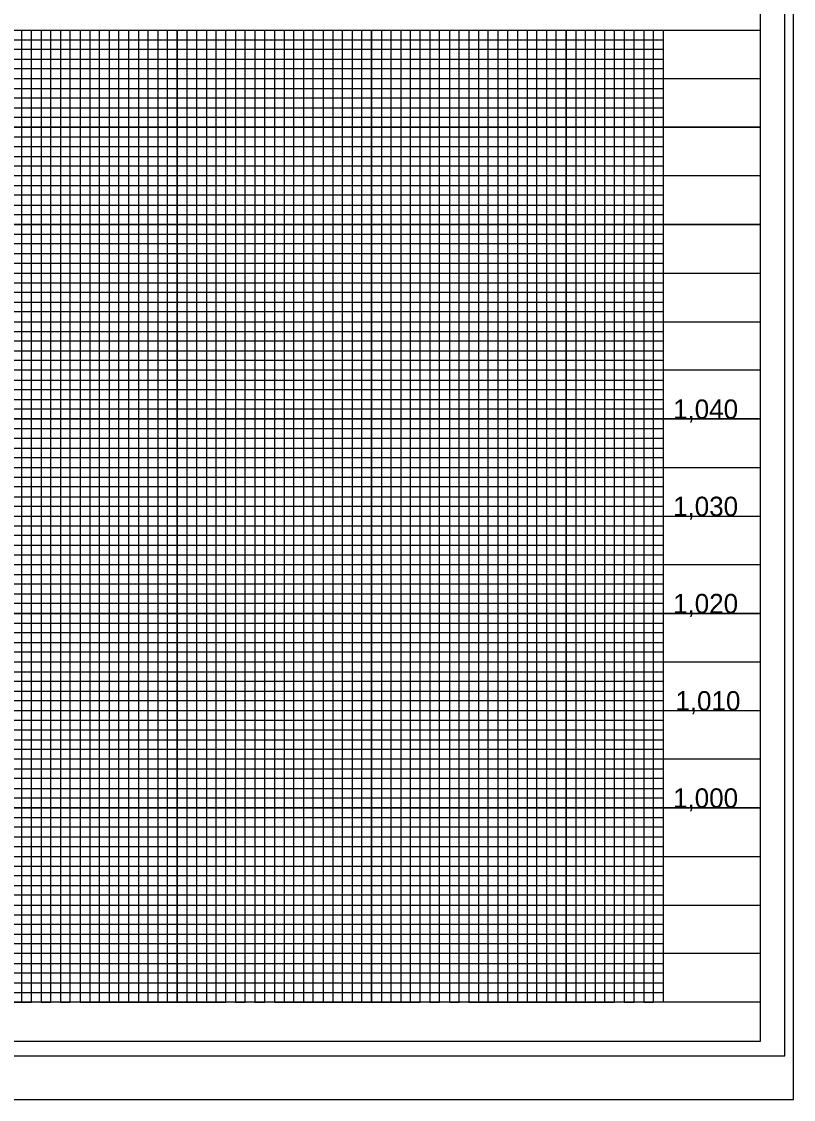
# Model space of a CAD drawing. Extents: x 1427348 to 1429459, y 856278 to 857378.
# Drawn here: x 1428884 to 1429281, y 856278 to 856832 of the extents above; entities that cross this region are included whole.
import ezdxf

# ---------------------------------------------------------------- set-up
doc = ezdxf.new("R2010")
doc.units = 0
for name, color, linetype in [('Exist Vertical Profile Vertical Axis Label', 7, 'Continuous'), ('Sheet Cutting Line CELL', 7, 'Continuous'), ('Sheet DOT Grid CELL', 7, 'Continuous'), ('Sheet Layout Profile Border Port 2', 7, 'Continuous'), ('Sheet Plot Border Inside CELL', 7, 'Continuous'), ('Sheet Plot Border Outside CELL', 7, 'Continuous'), ('Sheet Profile CELL', 7, 'Continuous'), ('Sheet Profile Grid Major CELL', 7, 'Continuous'), ('Sheet Profile Grid Middle CELL', 7, 'Continuous'), ('Sheet Profile Grid Minor CELL', 7, 'Continuous')]:
    doc.layers.add(name, color=color, linetype=linetype)

msp = doc.modelspace()

# ---------------------------------------------------------------- linework, layer by layer
at = {"layer": 'Sheet Cutting Line CELL'}
msp.add_line((1427596.99, 856277.58), (1429280.99, 856277.58), dxfattribs=at)
at = {"layer": 'Sheet DOT Grid CELL'}
for p, q in [((1427763.99, 856827.58), (1429263.88, 856827.58)), ((1428913.99, 856827.58), (1428913.99, 856327.58)), ((1428963.99, 856827.58), (1428963.99, 856327.58)), ((1429013.99, 856827.58), (1429013.99, 856327.58)), ((1429063.99, 856827.58), (1429063.99, 856327.58)), ((1429113.99, 856827.58), (1429113.99, 856327.58)), ((1429163.99, 856827.58), (1429163.99, 856327.58)), ((1429213.99, 856827.58), (1429213.99, 856327.58)), ((1427763.99, 856777.58), (1429263.88, 856777.58)), ((1428458.77, 856727.58), (1429263.88, 856727.58)), ((1428023.59, 856677.58), (1429263.88, 856677.58)), ((1428485.43, 856627.58), (1429263.88, 856627.58)), ((1428403.82, 856577.58), (1429263.88, 856577.58)), ((1427763.99, 856527.58), (1429263.88, 856527.58)), ((1427763.99, 856477.58), (1429263.88, 856477.58)), ((1427763.99, 856427.58), (1429263.88, 856427.58)), ((1427763.99, 856377.58), (1429263.88, 856377.58))]:
    msp.add_line(p, q, dxfattribs=at)
at = {"layer": 'Sheet Layout Profile Border Port 2'}
msp.add_lwpolyline([(1427813.99, 856827.58), (1429213.99, 856827.58), (1429213.99, 856327.58), (1427813.99, 856327.58)], close=True, dxfattribs=at)
at = {"layer": 'Sheet Plot Border Inside CELL'}
for p, q in [((1429276.49, 856300.03), (1429276.49, 857355.13)), ((1427609.99, 856300.03), (1429276.49, 856300.03))]:
    msp.add_line(p, q, dxfattribs=at)
at = {"layer": 'Sheet Plot Border Outside CELL'}
msp.add_lwpolyline([(1427596.99, 856277.58), (1429280.99, 856277.58), (1429280.99, 857377.58), (1427596.99, 857377.58)], close=True, dxfattribs=at)
at = {"layer": 'Sheet Profile CELL'}
for p, q in [((1427763.99, 856827.58), (1429263.99, 856827.58)), ((1429263.99, 856327.58), (1427763.99, 856327.58)), ((1427763.99, 856307.58), (1429263.99, 856307.58))]:
    msp.add_line(p, q, dxfattribs=at)
msp.add_lwpolyline([(1429263.99, 857347.58), (1427763.99, 857347.58), (1427763.99, 856307.58), (1429263.99, 856307.58)], close=True, dxfattribs=at)
at = {"layer": 'Sheet Profile Grid Major CELL'}
for p, q in [((1428863.99, 856827.58), (1428913.99, 856827.58)), ((1428963.99, 856827.58), (1429013.99, 856827.58)), ((1429063.99, 856827.58), (1429113.99, 856827.58)), ((1429163.99, 856827.58), (1429213.99, 856827.58)), ((1429163.99, 856327.58), (1429163.99, 856327.58))]:
    msp.add_line(p, q, dxfattribs=at)
for points in [[(1428863.99, 856827.58), (1428913.99, 856827.58), (1428913.99, 856327.58), (1428963.99, 856327.58), (1428963.99, 856827.58), (1429013.99, 856827.58), (1429013.99, 856327.58), (1429063.99, 856327.58), (1429063.99, 856827.58), (1429113.99, 856827.58), (1429113.99, 856327.58), (1429163.99, 856327.58), (1429163.99, 856327.58), (1429163.99, 856827.58), (1429213.99, 856827.58), (1429213.99, 856327.58)], [(1429263.99, 856777.58), (1427763.99, 856777.58)], [(1429263.99, 856727.58), (1428458.77, 856727.58)], [(1428023.59, 856677.58), (1429263.99, 856677.58)], [(1429263.99, 856627.58), (1428485.43, 856627.58)], [(1428403.82, 856577.58), (1429263.99, 856577.58)], [(1429263.99, 856527.58), (1427763.99, 856527.58), (1427763.99, 856477.58), (1429263.99, 856477.58)], [(1429263.99, 856427.58), (1427763.99, 856427.58), (1427763.99, 856427.58), (1427763.99, 856377.58), (1429263.99, 856377.58)], [(1429263.99, 856327.58), (1427763.99, 856327.58)]]:
    msp.add_lwpolyline(points, dxfattribs=at)
at = {"layer": 'Sheet Profile Grid Middle CELL'}
for points in [[(1428838.99, 856327.58), (1428888.99, 856327.58), (1428888.99, 856827.58), (1428938.99, 856827.58), (1428938.99, 856327.58), (1428988.99, 856327.58), (1428988.99, 856827.58), (1429038.99, 856827.58), (1429038.99, 856327.58), (1429088.99, 856327.58), (1429088.99, 856827.58), (1429138.99, 856827.58), (1429138.99, 856327.58), (1429188.99, 856327.58), (1429188.99, 856827.58)], [(1427763.99, 856802.58), (1429263.99, 856802.58)], [(1429263.99, 856752.58), (1428458.77, 856752.58)], [(1428023.59, 856702.58), (1429263.99, 856702.58)], [(1429263.99, 856652.58), (1428485.43, 856652.58)], [(1428403.82, 856602.58), (1429263.99, 856602.58)], [(1429263.99, 856552.58), (1427763.99, 856552.58), (1427763.99, 856502.58), (1429263.99, 856502.58)], [(1429263.99, 856452.58), (1427763.99, 856452.58), (1427763.99, 856402.58), (1429263.99, 856402.58)], [(1429263.99, 856352.58), (1427763.99, 856352.58)]]:
    msp.add_lwpolyline(points, dxfattribs=at)
at = {"layer": 'Sheet Profile Grid Minor CELL'}
for p, q in [((1427813.99, 856822.58), (1429213.99, 856822.58)), ((1429213.99, 856817.58), (1427813.99, 856817.58)), ((1427813.99, 856812.58), (1429213.99, 856812.58)), ((1429213.99, 856807.58), (1427813.99, 856807.58)), ((1427813.99, 856797.58), (1429213.99, 856797.58)), ((1429213.99, 856792.58), (1427813.99, 856792.58)), ((1427813.99, 856787.58), (1429213.99, 856787.58)), ((1429213.99, 856782.58), (1427813.99, 856782.58)), ((1427813.99, 856772.58), (1429213.99, 856772.58)), ((1429213.99, 856767.58), (1427813.99, 856767.58)), ((1427813.99, 856762.58), (1429213.99, 856762.58)), ((1429213.99, 856757.58), (1428458.77, 856757.58)), ((1428458.77, 856747.58), (1429213.99, 856747.58)), ((1429213.99, 856742.58), (1428458.77, 856742.58)), ((1428458.77, 856737.58), (1429213.99, 856737.58)), ((1429213.99, 856732.58), (1428458.77, 856732.58)), ((1428458.77, 856722.58), (1429213.99, 856722.58)), ((1429213.99, 856717.58), (1428009.5, 856717.58)), ((1427813.99, 856712.58), (1429213.99, 856712.58)), ((1429213.99, 856707.58), (1428023.59, 856707.58)), ((1428023.59, 856697.58), (1429213.99, 856697.58)), ((1429213.99, 856692.58), (1428023.59, 856692.58)), ((1428023.59, 856687.58), (1429213.99, 856687.58)), ((1429213.99, 856682.58), (1428023.59, 856682.58)), ((1428362.68, 856672.58), (1429213.99, 856672.58)), ((1429213.99, 856667.58), (1428485.43, 856667.58)), ((1428485.43, 856662.58), (1429213.99, 856662.58)), ((1429213.99, 856657.58), (1428485.43, 856657.58)), ((1428485.43, 856647.58), (1429213.99, 856647.58)), ((1429213.99, 856642.58), (1428485.43, 856642.58)), ((1428485.43, 856637.58), (1429213.99, 856637.58)), ((1429213.99, 856632.58), (1428485.43, 856632.66)), ((1427813.99, 856622.58), (1429213.99, 856622.58)), ((1429213.99, 856617.58), (1427813.99, 856617.58)), ((1427813.99, 856612.58), (1429213.99, 856612.58)), ((1429213.99, 856607.58), (1428403.82, 856607.58)), ((1428403.82, 856597.58), (1429213.99, 856597.58)), ((1429213.99, 856592.58), (1428403.82, 856592.58)), ((1428403.82, 856587.58), (1429213.99, 856587.58)), ((1429213.99, 856582.58), (1428403.82, 856582.58)), ((1428403.82, 856572.58), (1429213.99, 856572.58)), ((1429213.99, 856567.58), (1428403.82, 856567.58)), ((1427813.99, 856562.58), (1429213.99, 856562.58)), ((1429213.99, 856557.58), (1427813.99, 856557.58)), ((1427813.99, 856547.58), (1429213.99, 856547.58)), ((1429213.99, 856542.58), (1427813.99, 856542.58)), ((1427813.99, 856537.58), (1429213.99, 856537.58)), ((1429213.99, 856532.58), (1427813.99, 856532.58)), ((1427813.99, 856522.58), (1429213.99, 856522.58)), ((1429213.99, 856517.58), (1427813.99, 856517.58)), ((1427813.99, 856512.58), (1429213.99, 856512.58)), ((1429213.99, 856507.58), (1427813.99, 856507.58)), ((1427813.99, 856497.58), (1429213.99, 856497.58)), ((1429213.99, 856492.58), (1427813.99, 856492.58)), ((1427813.99, 856487.58), (1429213.99, 856487.58)), ((1429213.99, 856482.58), (1427813.99, 856482.58)), ((1427813.99, 856472.58), (1429213.99, 856472.58)), ((1429213.99, 856467.58), (1427813.99, 856467.58)), ((1427813.99, 856462.58), (1429213.99, 856462.58)), ((1429213.99, 856457.58), (1427813.99, 856457.58)), ((1427813.99, 856447.58), (1429213.99, 856447.58)), ((1429213.99, 856442.58), (1427813.99, 856442.58)), ((1427813.99, 856437.58), (1429213.99, 856437.58)), ((1429213.99, 856432.58), (1427813.99, 856432.58)), ((1427813.99, 856422.58), (1429213.99, 856422.58)), ((1429213.99, 856417.58), (1427813.99, 856417.58)), ((1427813.99, 856412.58), (1429213.99, 856412.58)), ((1429213.99, 856407.58), (1427813.99, 856407.58)), ((1427813.99, 856397.58), (1429213.99, 856397.58)), ((1429213.99, 856392.58), (1427813.99, 856392.58)), ((1427813.99, 856387.58), (1429213.99, 856387.58)), ((1429213.99, 856382.58), (1427813.99, 856382.58)), ((1427813.99, 856372.58), (1429213.99, 856372.58)), ((1429213.99, 856367.58), (1427813.99, 856367.58)), ((1427813.99, 856362.58), (1429213.99, 856362.58)), ((1429213.99, 856357.58), (1427813.99, 856357.58)), ((1427813.99, 856347.58), (1429213.99, 856347.58)), ((1429213.99, 856342.58), (1427813.99, 856342.58)), ((1427813.99, 856337.58), (1429213.99, 856337.58)), ((1427813.99, 856332.58), (1429213.99, 856332.58))]:
    msp.add_line(p, q, dxfattribs=at)
for points in [[(1428878.99, 856327.58), (1428883.99, 856327.58), (1428883.99, 856827.58), (1428893.99, 856827.58), (1428893.99, 856327.58), (1428898.99, 856327.58), (1428898.99, 856827.58), (1428903.99, 856827.58), (1428903.99, 856327.58), (1428908.99, 856327.58), (1428908.99, 856827.58), (1428918.99, 856827.58), (1428918.99, 856327.58), (1428923.99, 856327.58), (1428923.99, 856827.58), (1428928.99, 856827.58), (1428928.99, 856327.58), (1428933.99, 856327.58), (1428933.99, 856827.58), (1428943.99, 856827.58), (1428943.99, 856327.58), (1428948.99, 856327.58), (1428948.99, 856827.58), (1428953.99, 856827.58), (1428953.99, 856327.58)], [(1428953.99, 856327.58), (1428958.99, 856327.58), (1428958.99, 856827.58), (1428968.99, 856827.58), (1428968.99, 856327.58), (1428973.99, 856327.58), (1428973.99, 856827.58), (1428978.99, 856827.58), (1428978.99, 856327.58), (1428983.99, 856327.58), (1428983.99, 856827.58), (1428993.99, 856827.58), (1428993.99, 856327.58), (1428998.99, 856327.58), (1428998.99, 856827.58), (1429003.99, 856827.58), (1429003.99, 856327.58), (1429008.99, 856327.58), (1429008.99, 856827.58), (1429018.99, 856827.58), (1429018.99, 856327.58), (1429023.99, 856327.58), (1429023.99, 856827.58), (1429028.99, 856827.58), (1429028.99, 856327.58), (1429033.99, 856327.58), (1429033.99, 856827.58), (1429043.99, 856827.58), (1429043.99, 856327.58), (1429048.99, 856327.58), (1429048.99, 856827.58), (1429053.99, 856827.58), (1429053.99, 856327.58), (1429058.99, 856327.58), (1429058.99, 856827.58), (1429068.99, 856827.58), (1429068.99, 856327.58), (1429073.99, 856327.58), (1429073.99, 856827.58), (1429078.99, 856827.58), (1429078.99, 856327.58), (1429083.99, 856327.58), (1429083.99, 856827.58), (1429093.99, 856827.58), (1429093.99, 856327.58), (1429098.99, 856327.58), (1429098.99, 856827.58), (1429103.99, 856827.58), (1429103.99, 856327.58), (1429108.99, 856327.58), (1429108.99, 856827.58), (1429118.99, 856827.58), (1429118.99, 856327.58), (1429123.99, 856327.58), (1429123.99, 856827.58), (1429128.99, 856827.58), (1429128.99, 856327.58), (1429133.99, 856327.58), (1429133.99, 856827.58), (1429143.99, 856827.58), (1429143.99, 856327.58), (1429148.99, 856327.58), (1429148.99, 856827.58), (1429153.99, 856827.58), (1429153.99, 856327.58), (1429158.99, 856327.58), (1429158.99, 856827.58), (1429168.99, 856827.58), (1429168.99, 856327.58), (1429173.99, 856327.58), (1429173.99, 856827.58), (1429178.99, 856827.58), (1429178.99, 856327.58), (1429183.99, 856327.58), (1429183.99, 856827.58), (1429193.99, 856827.58), (1429193.99, 856327.58), (1429198.99, 856327.58), (1429198.99, 856827.58), (1429203.99, 856827.58), (1429203.99, 856327.58), (1429208.99, 856327.58), (1429208.99, 856827.58), (1429213.99, 856827.58)]]:
    msp.add_lwpolyline(points, dxfattribs=at)

# ---------------------------------------------------------------- texts
at = {"layer": 'Exist Vertical Profile Vertical Axis Label'}
for s, p in [('1,040', (1429219.05, 856627.58)), ('1,030', (1429219.05, 856577.58)), ('1,020', (1429219.05, 856527.58)), ('1,010', (1429220.25, 856477.58)), ('1,000', (1429219.05, 856427.58))]:
    msp.add_text(s, height=10, dxfattribs=at).set_placement(p)

doc.saveas('drawing.dxf')
